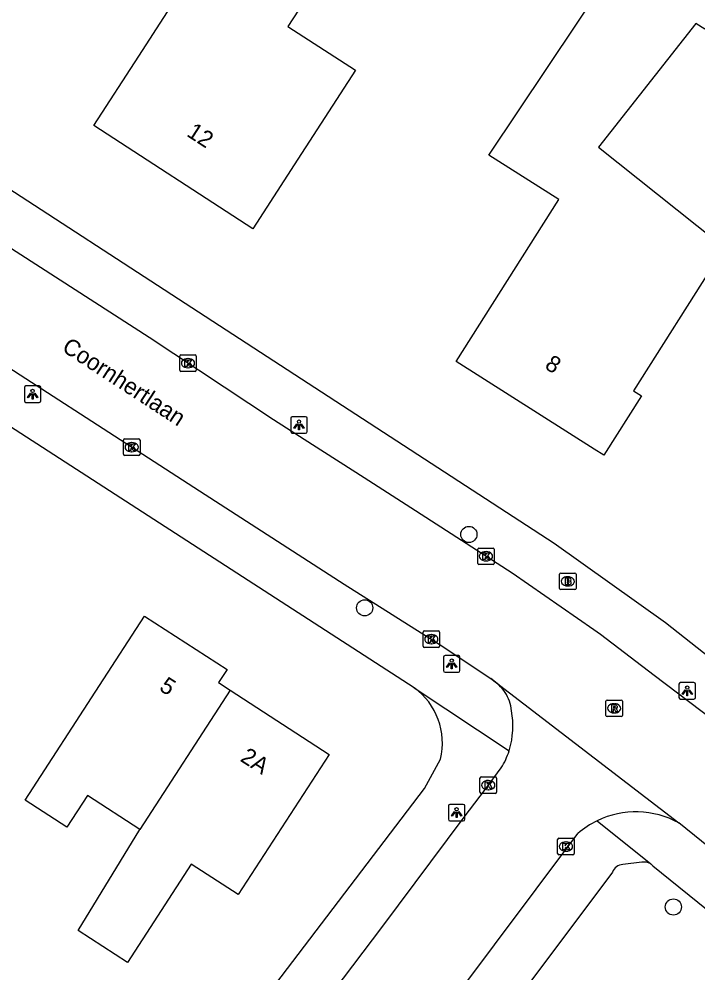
# Model space of a CAD drawing. Extents: x 161141 to 161601, y 381708 to 382245.
# Drawn here: x 161346.6 to 161387.6, y 381911 to 381968.7 of the extents above; entities that cross this region are included whole.
import ezdxf

# ---------------------------------------------------------------- set-up
doc = ezdxf.new("R2010")
doc.units = 0
for name, color, linetype in [('IMGEO_Boom', 7, 'Continuous'), ('IMGEO_Brandkraan', 7, 'Continuous'), ('IMGEO_Kolk', 7, 'Continuous'), ('IMGEO_Lichtpunt', 7, 'Continuous'), ('IMGEO_Openbare_ruimte_label', 7, 'Continuous'), ('IMGEO_Pand', 7, 'Continuous'), ('IMGEO_Pand_nummerreeks', 7, 'Continuous'), ('IMGEO_Rijbaan_lokaal_open', 7, 'Continuous'), ('IMGEO_Rioolput', 7, 'Continuous'), ('IMGEO_Voetpad_open', 7, 'Continuous')]:
    doc.layers.add(name, color=color, linetype=linetype)

msp = doc.modelspace()

# ---------------------------------------------------------------- linework, layer by layer
at = {"layer": 'IMGEO_Boom'}
for centre in [(161373.765, 381937.525), (161367.465, 381933.088), (161386.123, 381915.011)]:
    msp.add_circle(centre, 0.489, dxfattribs=at)
at = {"layer": 'IMGEO_Brandkraan'}
for p, q in [((161379.239, 381934.265), (161379.239, 381935.117)), ((161379.314, 381935.191), (161380.166, 381935.191)), ((161379.727, 381934.971), (161379.752, 381934.971)), ((161380.24, 381935.117), (161380.24, 381934.265)), ((161379.75, 381934.411), (161379.725, 381934.411)), ((161380.166, 381934.191), (161379.314, 381934.191))]:
    msp.add_line(p, q, dxfattribs=at)
for points in [[(161379.239, 381934.265), (161379.239, 381935.117)], [(161379.314, 381935.191), (161380.166, 381935.191)], [(161380.24, 381935.117), (161380.24, 381934.265)], [(161379.587, 381934.891), (161379.587, 381934.491), (161379.8, 381934.491)], [(161379.818, 381934.891), (161379.587, 381934.891)], [(161379.766, 381934.81), (161379.712, 381934.81), (161379.712, 381934.734)], [(161379.712, 381934.734), (161379.765, 381934.734)], [(161379.774, 381934.658), (161379.712, 381934.658), (161379.712, 381934.577)], [(161379.712, 381934.577), (161379.774, 381934.577)], [(161380.166, 381934.191), (161379.314, 381934.191)]]:
    msp.add_lwpolyline(points, dxfattribs=at)
for centre, radius, start, end in [((161379.316, 381935.115), 0.0765, 91.55205, 178.44795), ((161379.316, 381935.115), 0.0765, 91.55205, 178.44795), ((161380.164, 381935.115), 0.0765, 1.55205, 88.44795), ((161380.164, 381935.115), 0.0765, 1.55205, 88.44795), ((161379.767, 381934.772), 0.0379, 267.82845, 90.93552), ((161379.775, 381934.617), 0.0404, 269.87594, 90.50774), ((161379.806, 381934.742), 0.251, 268.66757, 293.53466), ((161379.822, 381934.746), 0.145, 59.4692, 91.53667), ((161379.847, 381934.793), 0.0922, 285.51372, 58.15012), ((161379.852, 381934.601), 0.105, 301.31148, 78.98903), ((161379.316, 381934.267), 0.0765, 181.55205, 268.44795), ((161379.316, 381934.267), 0.0765, 181.55205, 268.44795), ((161380.164, 381934.267), 0.0765, 271.55205, 358.44795), ((161380.164, 381934.267), 0.0765, 271.55205, 358.44795)]:
    msp.add_arc(centre, radius, start, end, dxfattribs=at)
for centre, major_axis, ratio, start_param, end_param in [((161379.726, 381934.691), (-0.387, 0.002), 0.722429, 4.712389, 7.853982), ((161379.751, 381934.691), (-0.39, 0.002), 0.717154, 1.570796, 4.712389)]:
    msp.add_ellipse(centre, major_axis=major_axis, ratio=ratio, start_param=start_param, end_param=end_param, dxfattribs=at)
at = {"layer": 'IMGEO_Kolk'}
for p, q in [((161356.285, 381947.451), (161356.285, 381948.303)), ((161356.36, 381948.377), (161357.212, 381948.377)), ((161357.286, 381948.303), (161357.286, 381947.451)), ((161356.773, 381948.157), (161356.798, 381948.157)), ((161357.212, 381947.377), (161356.36, 381947.377)), ((161356.796, 381947.597), (161356.771, 381947.597)), ((161352.887, 381942.372), (161352.887, 381943.224)), ((161352.962, 381943.298), (161353.814, 381943.298)), ((161353.375, 381943.078), (161353.4, 381943.078)), ((161353.888, 381943.224), (161353.888, 381942.372)), ((161353.398, 381942.518), (161353.373, 381942.518)), ((161353.814, 381942.298), (161352.962, 381942.298)), ((161374.37, 381936.704), (161375.222, 381936.704)), ((161374.295, 381935.778), (161374.295, 381936.63)), ((161374.783, 381936.484), (161374.808, 381936.484)), ((161375.296, 381936.63), (161375.296, 381935.778)), ((161375.222, 381935.704), (161374.37, 381935.704)), ((161374.806, 381935.924), (161374.781, 381935.924)), ((161370.995, 381930.77), (161370.995, 381931.622)), ((161371.07, 381931.696), (161371.922, 381931.696)), ((161371.483, 381931.476), (161371.508, 381931.476)), ((161371.996, 381931.622), (161371.996, 381930.77)), ((161371.506, 381930.916), (161371.481, 381930.916)), ((161371.922, 381930.696), (161371.07, 381930.696)), ((161374.509, 381922.874), (161375.361, 381922.874)), ((161374.434, 381921.948), (161374.434, 381922.8)), ((161374.922, 381922.654), (161374.947, 381922.654)), ((161375.435, 381922.8), (161375.435, 381921.948)), ((161375.361, 381921.874), (161374.509, 381921.874)), ((161374.945, 381922.094), (161374.92, 381922.094)), ((161379.129, 381918.236), (161379.129, 381919.088)), ((161379.204, 381919.162), (161380.056, 381919.162)), ((161379.617, 381918.942), (161379.642, 381918.942)), ((161380.13, 381919.088), (161380.13, 381918.236)), ((161379.64, 381918.382), (161379.615, 381918.382)), ((161380.056, 381918.162), (161379.204, 381918.162))]:
    msp.add_line(p, q, dxfattribs=at)
for points in [[(161356.285, 381947.451), (161356.285, 381948.303)], [(161356.36, 381948.377), (161357.212, 381948.377)], [(161357.286, 381948.303), (161357.286, 381947.451)], [(161356.606, 381948.077), (161356.729, 381948.077), (161356.729, 381947.926), (161356.859, 381948.077), (161357.023, 381948.077), (161356.877, 381947.926), (161357.03, 381947.677), (161356.878, 381947.677), (161356.793, 381947.841), (161356.729, 381947.774), (161356.729, 381947.677), (161356.606, 381947.677), (161356.606, 381948.077)], [(161357.212, 381947.377), (161356.36, 381947.377)], [(161352.887, 381942.372), (161352.887, 381943.224)], [(161352.962, 381943.298), (161353.814, 381943.298)], [(161353.208, 381942.998), (161353.331, 381942.998), (161353.331, 381942.847), (161353.461, 381942.998), (161353.625, 381942.998), (161353.479, 381942.847), (161353.632, 381942.598), (161353.48, 381942.598), (161353.395, 381942.762), (161353.331, 381942.695), (161353.331, 381942.598), (161353.208, 381942.598), (161353.208, 381942.998)], [(161353.888, 381943.224), (161353.888, 381942.372)], [(161353.814, 381942.298), (161352.962, 381942.298)], [(161374.37, 381936.704), (161375.222, 381936.704)], [(161374.295, 381935.778), (161374.295, 381936.63)], [(161374.616, 381936.404), (161374.739, 381936.404), (161374.739, 381936.253), (161374.869, 381936.404), (161375.033, 381936.404), (161374.887, 381936.253), (161375.04, 381936.004), (161374.888, 381936.004), (161374.803, 381936.168), (161374.739, 381936.101), (161374.739, 381936.004), (161374.616, 381936.004), (161374.616, 381936.404)], [(161375.296, 381936.63), (161375.296, 381935.778)], [(161375.222, 381935.704), (161374.37, 381935.704)], [(161370.995, 381930.77), (161370.995, 381931.622)], [(161371.07, 381931.696), (161371.922, 381931.696)], [(161371.996, 381931.622), (161371.996, 381930.77)], [(161371.316, 381931.396), (161371.439, 381931.396), (161371.439, 381931.245), (161371.569, 381931.396), (161371.733, 381931.396), (161371.587, 381931.245), (161371.74, 381930.996), (161371.588, 381930.996), (161371.503, 381931.16), (161371.439, 381931.093), (161371.439, 381930.996), (161371.316, 381930.996), (161371.316, 381931.396)], [(161371.922, 381930.696), (161371.07, 381930.696)], [(161374.509, 381922.874), (161375.361, 381922.874)], [(161374.434, 381921.948), (161374.434, 381922.8)], [(161374.755, 381922.574), (161374.878, 381922.574), (161374.878, 381922.423), (161375.008, 381922.574), (161375.172, 381922.574), (161375.026, 381922.423), (161375.179, 381922.174), (161375.027, 381922.174), (161374.942, 381922.338), (161374.878, 381922.271), (161374.878, 381922.174), (161374.755, 381922.174), (161374.755, 381922.574)], [(161375.435, 381922.8), (161375.435, 381921.948)], [(161375.361, 381921.874), (161374.509, 381921.874)], [(161379.129, 381918.236), (161379.129, 381919.088)], [(161379.204, 381919.162), (161380.056, 381919.162)], [(161379.45, 381918.862), (161379.573, 381918.862), (161379.573, 381918.711), (161379.703, 381918.862), (161379.867, 381918.862), (161379.721, 381918.711), (161379.874, 381918.462), (161379.722, 381918.462), (161379.637, 381918.626), (161379.573, 381918.559), (161379.573, 381918.462), (161379.45, 381918.462), (161379.45, 381918.862)], [(161380.13, 381919.088), (161380.13, 381918.236)], [(161380.056, 381918.162), (161379.204, 381918.162)]]:
    msp.add_lwpolyline(points, dxfattribs=at)
for centre, start, end in [((161356.362, 381948.301), 91.55205, 178.44795), ((161356.362, 381948.301), 91.55205, 178.44795), ((161357.21, 381948.301), 1.55205, 88.44795), ((161357.21, 381948.301), 1.55205, 88.44795), ((161356.362, 381947.453), 181.55205, 268.44795), ((161356.362, 381947.453), 181.55205, 268.44795), ((161357.21, 381947.453), 271.55205, 358.44795), ((161357.21, 381947.453), 271.55205, 358.44795), ((161352.964, 381943.222), 91.55205, 178.44795), ((161352.964, 381943.222), 91.55205, 178.44795), ((161353.812, 381943.222), 1.55205, 88.44795), ((161353.812, 381943.222), 1.55205, 88.44795), ((161352.964, 381942.374), 181.55205, 268.44795), ((161352.964, 381942.374), 181.55205, 268.44795), ((161353.812, 381942.374), 271.55205, 358.44795), ((161353.812, 381942.374), 271.55205, 358.44795), ((161374.372, 381936.628), 91.55205, 178.44795), ((161374.372, 381936.628), 91.55205, 178.44795), ((161375.22, 381936.628), 1.55205, 88.44795), ((161375.22, 381936.628), 1.55205, 88.44795), ((161374.372, 381935.78), 181.55205, 268.44795), ((161374.372, 381935.78), 181.55205, 268.44795), ((161375.22, 381935.78), 271.55205, 358.44795), ((161375.22, 381935.78), 271.55205, 358.44795), ((161371.072, 381931.62), 91.55205, 178.44795), ((161371.072, 381931.62), 91.55205, 178.44795), ((161371.92, 381931.62), 1.55205, 88.44795), ((161371.92, 381931.62), 1.55205, 88.44795), ((161371.072, 381930.772), 181.55205, 268.44795), ((161371.072, 381930.772), 181.55205, 268.44795), ((161371.92, 381930.772), 271.55205, 358.44795), ((161371.92, 381930.772), 271.55205, 358.44795), ((161374.511, 381922.798), 91.55205, 178.44795), ((161374.511, 381922.798), 91.55205, 178.44795), ((161375.359, 381922.798), 1.55205, 88.44795), ((161375.359, 381922.798), 1.55205, 88.44795), ((161374.511, 381921.95), 181.55205, 268.44795), ((161374.511, 381921.95), 181.55205, 268.44795), ((161375.359, 381921.95), 271.55205, 358.44795), ((161375.359, 381921.95), 271.55205, 358.44795), ((161379.206, 381919.086), 91.55205, 178.44795), ((161379.206, 381919.086), 91.55205, 178.44795), ((161380.054, 381919.086), 1.55205, 88.44795), ((161380.054, 381919.086), 1.55205, 88.44795), ((161379.206, 381918.238), 181.55205, 268.44795), ((161379.206, 381918.238), 181.55205, 268.44795), ((161380.054, 381918.238), 271.55205, 358.44795), ((161380.054, 381918.238), 271.55205, 358.44795)]:
    msp.add_arc(centre, 0.0765, start, end, dxfattribs=at)
for centre, major_axis, ratio, start_param, end_param in [((161356.772, 381947.877), (-0.387, 0.002), 0.722429, 4.712389, 7.853982), ((161356.797, 381947.877), (-0.39, 0.002), 0.717154, 1.570796, 4.712389), ((161353.374, 381942.798), (-0.387, 0.002), 0.722429, 4.712389, 7.853982), ((161353.399, 381942.798), (-0.39, 0.002), 0.717154, 1.570796, 4.712389), ((161374.782, 381936.204), (-0.387, 0.002), 0.722429, 4.712389, 7.853982), ((161374.807, 381936.204), (-0.39, 0.002), 0.717154, 1.570796, 4.712389), ((161371.482, 381931.196), (-0.387, 0.002), 0.722429, 4.712389, 7.853982), ((161371.507, 381931.196), (-0.39, 0.002), 0.717154, 1.570796, 4.712389), ((161374.921, 381922.374), (-0.387, 0.002), 0.722429, 4.712389, 7.853982), ((161374.946, 381922.374), (-0.39, 0.002), 0.717154, 1.570796, 4.712389), ((161379.616, 381918.662), (-0.387, 0.002), 0.722429, 4.712389, 7.853982), ((161379.641, 381918.662), (-0.39, 0.002), 0.717154, 1.570796, 4.712389)]:
    msp.add_ellipse(centre, major_axis=major_axis, ratio=ratio, start_param=start_param, end_param=end_param, dxfattribs=at)
at = {"layer": 'IMGEO_Lichtpunt'}
for p, q in [((161347.801, 381946.498), (161346.993, 381946.498)), ((161347.801, 381946.498), (161346.993, 381946.498)), ((161346.899, 381946.403), (161346.899, 381945.596)), ((161346.899, 381946.403), (161346.899, 381945.596)), ((161347.895, 381945.596), (161347.895, 381946.403)), ((161347.895, 381945.596), (161347.895, 381946.403)), ((161346.993, 381945.502), (161347.801, 381945.502)), ((161346.993, 381945.502), (161347.801, 381945.502)), ((161362.997, 381944.545), (161362.997, 381943.738)), ((161362.997, 381944.545), (161362.997, 381943.738)), ((161363.899, 381944.64), (161363.091, 381944.64)), ((161363.899, 381944.64), (161363.091, 381944.64)), ((161363.993, 381943.738), (161363.993, 381944.545)), ((161363.993, 381943.738), (161363.993, 381944.545)), ((161363.091, 381943.644), (161363.899, 381943.644)), ((161363.091, 381943.644), (161363.899, 381943.644)), ((161372.227, 381930.104), (161372.227, 381929.297)), ((161372.227, 381930.104), (161372.227, 381929.297)), ((161373.129, 381930.199), (161372.321, 381930.199)), ((161373.129, 381930.199), (161372.321, 381930.199)), ((161373.223, 381929.297), (161373.223, 381930.104)), ((161373.223, 381929.297), (161373.223, 381930.104)), ((161372.321, 381929.203), (161373.129, 381929.203)), ((161372.321, 381929.203), (161373.129, 381929.203)), ((161386.461, 381928.475), (161386.461, 381927.668)), ((161386.461, 381928.475), (161386.461, 381927.668)), ((161387.363, 381928.57), (161386.555, 381928.57)), ((161387.363, 381928.57), (161386.555, 381928.57)), ((161387.457, 381927.668), (161387.457, 381928.475)), ((161387.457, 381927.668), (161387.457, 381928.475)), ((161386.555, 381927.574), (161387.363, 381927.574)), ((161386.555, 381927.574), (161387.363, 381927.574)), ((161372.525, 381921.116), (161372.525, 381920.309)), ((161372.525, 381921.116), (161372.525, 381920.309)), ((161373.427, 381921.211), (161372.619, 381921.211)), ((161373.427, 381921.211), (161372.619, 381921.211)), ((161373.521, 381920.309), (161373.521, 381921.116)), ((161373.521, 381920.309), (161373.521, 381921.116)), ((161372.619, 381920.215), (161373.427, 381920.215)), ((161372.619, 381920.215), (161373.427, 381920.215))]:
    msp.add_line(p, q, dxfattribs=at)
for points in [[(161347.273, 381946.067), (161347.312, 381946.039), (161347.124, 381945.777), (161347.086, 381945.804), (161347.273, 381946.067)], [(161347.375, 381946.019), (161347.422, 381946.019), (161347.422, 381945.697), (161347.375, 381945.697), (161347.375, 381946.019)], [(161347.485, 381946.039), (161347.523, 381946.066), (161347.71, 381945.804), (161347.671, 381945.776), (161347.485, 381946.039)], [(161363.371, 381944.209), (161363.41, 381944.181), (161363.222, 381943.919), (161363.184, 381943.946), (161363.371, 381944.209)], [(161363.473, 381944.161), (161363.52, 381944.161), (161363.52, 381943.839), (161363.473, 381943.839), (161363.473, 381944.161)], [(161363.583, 381944.181), (161363.621, 381944.208), (161363.808, 381943.946), (161363.769, 381943.918), (161363.583, 381944.181)], [(161372.601, 381929.768), (161372.64, 381929.74), (161372.452, 381929.478), (161372.414, 381929.505), (161372.601, 381929.768)], [(161372.813, 381929.74), (161372.851, 381929.767), (161373.038, 381929.505), (161372.999, 381929.477), (161372.813, 381929.74)], [(161372.703, 381929.72), (161372.75, 381929.72), (161372.75, 381929.398), (161372.703, 381929.398), (161372.703, 381929.72)], [(161386.835, 381928.139), (161386.874, 381928.111), (161386.686, 381927.849), (161386.648, 381927.876), (161386.835, 381928.139)], [(161386.937, 381928.091), (161386.984, 381928.091), (161386.984, 381927.769), (161386.937, 381927.769), (161386.937, 381928.091)], [(161387.047, 381928.111), (161387.085, 381928.138), (161387.272, 381927.876), (161387.233, 381927.848), (161387.047, 381928.111)], [(161372.899, 381920.78), (161372.938, 381920.752), (161372.75, 381920.49), (161372.712, 381920.517), (161372.899, 381920.78)], [(161373.001, 381920.732), (161373.048, 381920.732), (161373.048, 381920.41), (161373.001, 381920.41), (161373.001, 381920.732)], [(161373.111, 381920.752), (161373.149, 381920.779), (161373.336, 381920.517), (161373.297, 381920.489), (161373.111, 381920.752)]]:
    msp.add_lwpolyline(points, dxfattribs=at)
for centre in [(161347.398, 381946.201), (161363.496, 381944.343), (161372.726, 381929.902), (161386.96, 381928.273), (161373.024, 381920.914)]:
    msp.add_circle(centre, 0.0994, dxfattribs=at)
for centre, start, end in [((161346.993, 381946.403), 90, 180), ((161346.993, 381946.403), 90, 180), ((161347.801, 381946.403), 0, 90), ((161347.801, 381946.403), 0, 90), ((161346.993, 381945.596), 180, 270), ((161346.993, 381945.596), 180, 270), ((161347.801, 381945.596), 270, 0), ((161347.801, 381945.596), 270, 360), ((161363.091, 381944.545), 90, 180), ((161363.091, 381944.545), 90, 180), ((161363.899, 381944.545), 0, 90), ((161363.899, 381944.545), 0, 90), ((161363.091, 381943.738), 180, 270), ((161363.091, 381943.738), 180, 270), ((161363.899, 381943.738), 270, 0), ((161363.899, 381943.738), 270, 360), ((161372.321, 381930.104), 90, 180), ((161372.321, 381930.104), 90, 180), ((161373.129, 381930.104), 0, 90), ((161373.129, 381930.104), 0, 90), ((161372.321, 381929.297), 180, 270), ((161372.321, 381929.297), 180, 270), ((161373.129, 381929.297), 270, 0), ((161373.129, 381929.297), 270, 360), ((161386.555, 381928.475), 90, 180), ((161386.555, 381928.475), 90, 180), ((161387.363, 381928.475), 0, 90), ((161387.363, 381928.475), 0, 90), ((161386.555, 381927.668), 180, 270), ((161386.555, 381927.668), 180, 270), ((161387.363, 381927.668), 270, 0), ((161387.363, 381927.668), 270, 360), ((161372.619, 381921.116), 90, 180), ((161372.619, 381921.116), 90, 180), ((161373.427, 381921.116), 0, 90), ((161373.427, 381921.116), 0, 90), ((161372.619, 381920.309), 180, 270), ((161372.619, 381920.309), 180, 270), ((161373.427, 381920.309), 270, 0), ((161373.427, 381920.309), 270, 360)]:
    msp.add_arc(centre, 0.0946, start, end, dxfattribs=at)
at = {"layer": 'IMGEO_Pand'}
for points in [[(161359.985, 381975.96), (161365.513, 381972.374), (161362.821, 381968.223), (161366.916, 381965.576), (161363.429, 381960.199), (161360.708, 381956.003), (161351.088, 381962.243), (161353.809, 381966.438), (161357.287, 381971.8), (161359.985, 381975.96)], [(161379.203, 381957.768), (161374.963, 381960.456), (161383.849, 381973.742), (161389.01, 381970.341), (161388.242, 381969.367), (161388.689, 381969.074), (161388.021, 381968.053), (161387.483, 381968.405), (161381.588, 381960.931), (161388.738, 381955.254), (161388.686, 381955.172), (161388.261, 381954.502), (161388.772, 381954.178), (161383.721, 381946.207), (161384.189, 381945.91), (161381.912, 381942.316), (161381.345, 381942.675), (161372.992, 381947.969), (161379.203, 381957.768)], [(161353.883, 381919.687), (161350.705, 381921.748), (161349.464, 381919.835), (161346.947, 381921.467), (161351.442, 381928.397), (161354.162, 381932.591), (161359.145, 381929.359), (161358.634, 381928.571), (161359.346, 381928.109)], [(161359.346, 381928.109), (161365.323, 381924.232), (161359.827, 381915.759), (161356.981, 381917.605), (161353.123, 381911.657), (161350.154, 381913.584), (161353.883, 381919.687)], [(161359.346, 381928.109), (161353.883, 381919.687)]]:
    msp.add_lwpolyline(points, dxfattribs=at)
at = {"layer": 'IMGEO_Rijbaan_lokaal_open'}
for points in [[(161278.323, 381991.478), (161299.753, 381977.533), (161307.482, 381972.536), (161311.114, 381970.18), (161315.062, 381967.62), (161315.173, 381967.548), (161318.89, 381965.138), (161327.462, 381959.489), (161330.866, 381957.332), (161337.714, 381952.958), (161346.638, 381947.161), (161350.625, 381944.584), (161357.825, 381939.931), (161366.222, 381934.52), (161372.037, 381930.857), (161375.083, 381928.811)], [(161430.53, 381892.26), (161428.93, 381893.541), (161416.582, 381903.762), (161409.42, 381909.443), (161405.146, 381912.95), (161401.483, 381915.955), (161397.742, 381918.904), (161394.58, 381921.397), (161388.533, 381926.301), (161384.971, 381929.006), (161381.728, 381931.469), (161381.315, 381931.756), (161376.383, 381935.18), (161370.251, 381939.135), (161367.432, 381940.939), (161364.318, 381942.933), (161361.946, 381944.451), (161354.44, 381949.434), (161345.5, 381955.194), (161345.132, 381955.433), (161341.968, 381957.49), (161334.965, 381962.043), (161325.373, 381968.263), (161318.237, 381972.89)], [(161375.083, 381928.811), (161386.448, 381920.091)], [(161375.58, 381928.429), (161375.083, 381928.811)], [(161347.78, 381886.211), (161351.589, 381891.33), (161355.178, 381896.112), (161357.581, 381899.312), (161358.116, 381900.025), (161368.51, 381913.776), (161373.481, 381920.434), (161374.759, 381922.138), (161375.72, 381923.419)], [(161426.69, 381887.564), (161425.057, 381888.885), (161404.152, 381905.797), (161399.947, 381909.192), (161394.957, 381913.221), (161391.403, 381916.091), (161386.448, 381920.091)], [(161372.8, 381909.362), (161380.355, 381919.457)]]:
    msp.add_lwpolyline(points, dxfattribs=at)
for centre, radius, start, end in [((161373.726, 381926.514), 2.665, 20.4952, 45.93725), ((161370.758, 381925.969), 5.662, 351.03296, 15.12768), ((161371.818, 381925.841), 4.594, 342.30493, 350.54839), ((161371.797, 381925.858), 4.62, 328.1286, 342.18662), ((161383.857, 381915.406), 5.354, 61.05531, 115.87601), ((161383.842, 381915.422), 5.333, 115.81415, 130.83655)]:
    msp.add_arc(centre, radius, start, end, dxfattribs=at)
at = {"layer": 'IMGEO_Rioolput'}
for p, q in [((161382.043, 381926.591), (161382.043, 381927.443)), ((161382.118, 381927.517), (161382.97, 381927.517)), ((161383.044, 381927.443), (161383.044, 381926.591)), ((161382.531, 381927.297), (161382.556, 381927.297)), ((161382.97, 381926.517), (161382.118, 381926.517)), ((161382.554, 381926.737), (161382.529, 381926.737))]:
    msp.add_line(p, q, dxfattribs=at)
for points in [[(161382.043, 381926.591), (161382.043, 381927.443)], [(161382.118, 381927.517), (161382.97, 381927.517)], [(161383.044, 381927.443), (161383.044, 381926.591)], [(161382.632, 381927.215), (161382.38, 381927.217), (161382.38, 381926.817)], [(161382.38, 381926.817), (161382.504, 381926.817), (161382.504, 381926.979), (161382.515, 381926.979)], [(161382.558, 381927.136), (161382.504, 381927.136), (161382.504, 381927.055)], [(161382.504, 381927.055), (161382.556, 381927.055)], [(161382.562, 381926.95), (161382.633, 381926.817), (161382.773, 381926.817), (161382.708, 381926.943)], [(161382.97, 381926.517), (161382.118, 381926.517)]]:
    msp.add_lwpolyline(points, dxfattribs=at)
for centre, radius, start, end in [((161382.12, 381927.441), 0.0765, 91.55205, 178.44795), ((161382.12, 381927.441), 0.0765, 91.55205, 178.44795), ((161382.968, 381927.441), 0.0765, 1.55205, 88.44795), ((161382.968, 381927.441), 0.0765, 1.55205, 88.44795), ((161382.514, 381926.926), 0.0533, 26.02933, 88.69889), ((161382.54, 381927.244), 0.19, 274.7715, 282.96867), ((161382.564, 381927.04), 0.0964, 77.00612, 93.18647), ((161382.578, 381927.097), 0.0378, 276.66336, 79.67722), ((161382.631, 381927.105), 0.109, 350.36119, 89.41601), ((161382.629, 381927.105), 0.112, 277.58423, 350.98172), ((161382.613, 381926.89), 0.108, 29.51342, 73.79051), ((161382.12, 381926.593), 0.0765, 181.55205, 268.44795), ((161382.12, 381926.593), 0.0765, 181.55205, 268.44795), ((161382.968, 381926.593), 0.0765, 271.55205, 358.44795), ((161382.968, 381926.593), 0.0765, 271.55205, 358.44795)]:
    msp.add_arc(centre, radius, start, end, dxfattribs=at)
for centre, major_axis, ratio, start_param, end_param in [((161382.53, 381927.017), (-0.387, 0.002), 0.722429, 4.712389, 7.853982), ((161382.555, 381927.017), (-0.39, 0.002), 0.717154, 1.570796, 4.712389)]:
    msp.add_ellipse(centre, major_axis=major_axis, ratio=ratio, start_param=start_param, end_param=end_param, dxfattribs=at)
at = {"layer": 'IMGEO_Voetpad_open'}
for points in [[(161278.294, 382002.287), (161281.877, 382000), (161299.823, 381988.353), (161310.674, 381981.109), (161322.611, 381973.432), (161322.712, 381973.551), (161378.924, 381936.994), (161385.641, 381932.206), (161392.817, 381926.552), (161429.313, 381896.994)], [(161370.462, 381928.258), (161276.309, 381989.126)], [(161370.462, 381928.258), (161376.195, 381924.445)], [(161342.481, 381884.773), (161344.76, 381887.264), (161354.145, 381899.917), (161371.073, 381922.177), (161372.043, 381923.95)], [(161381.52, 381920.223), (161384.753, 381917.612)], [(161384.224, 381917.711), (161383.062, 381917.586)], [(161382.438, 381917.119), (161355.077, 381880.626)], [(161384.753, 381917.612), (161384.887, 381917.504), (161410.212, 381897.05)]]:
    msp.add_lwpolyline(points, dxfattribs=at)
for centre, radius, start, end in [((161368.047, 381924.928), 4.114, 346.25108, 54.05435), ((161384.363, 381916.993), 0.731, 57.80114, 100.99879), ((161383.15, 381916.818), 0.773, 96.54228, 157.0799)]:
    msp.add_arc(centre, radius, start, end, dxfattribs=at)

# ---------------------------------------------------------------- texts
at = {"layer": 'IMGEO_Openbare_ruimte_label'}
msp.add_text('Coornhertlaan', height=1, rotation=326.91369, dxfattribs=at).set_placement((161349.104, 381948.652))
at = {"layer": 'IMGEO_Pand_nummerreeks'}
for s, rotation, p in [('12', 327.03201, (161356.65, 381961.639)), ('8', 327.63361, (161378.289, 381947.595)), ('5', 327.03234, (161354.994, 381928.142)), ('2A', 327.46063, (161359.888, 381923.863))]:
    msp.add_text(s, height=1, rotation=rotation, dxfattribs=at).set_placement(p)

doc.saveas('drawing.dxf')
